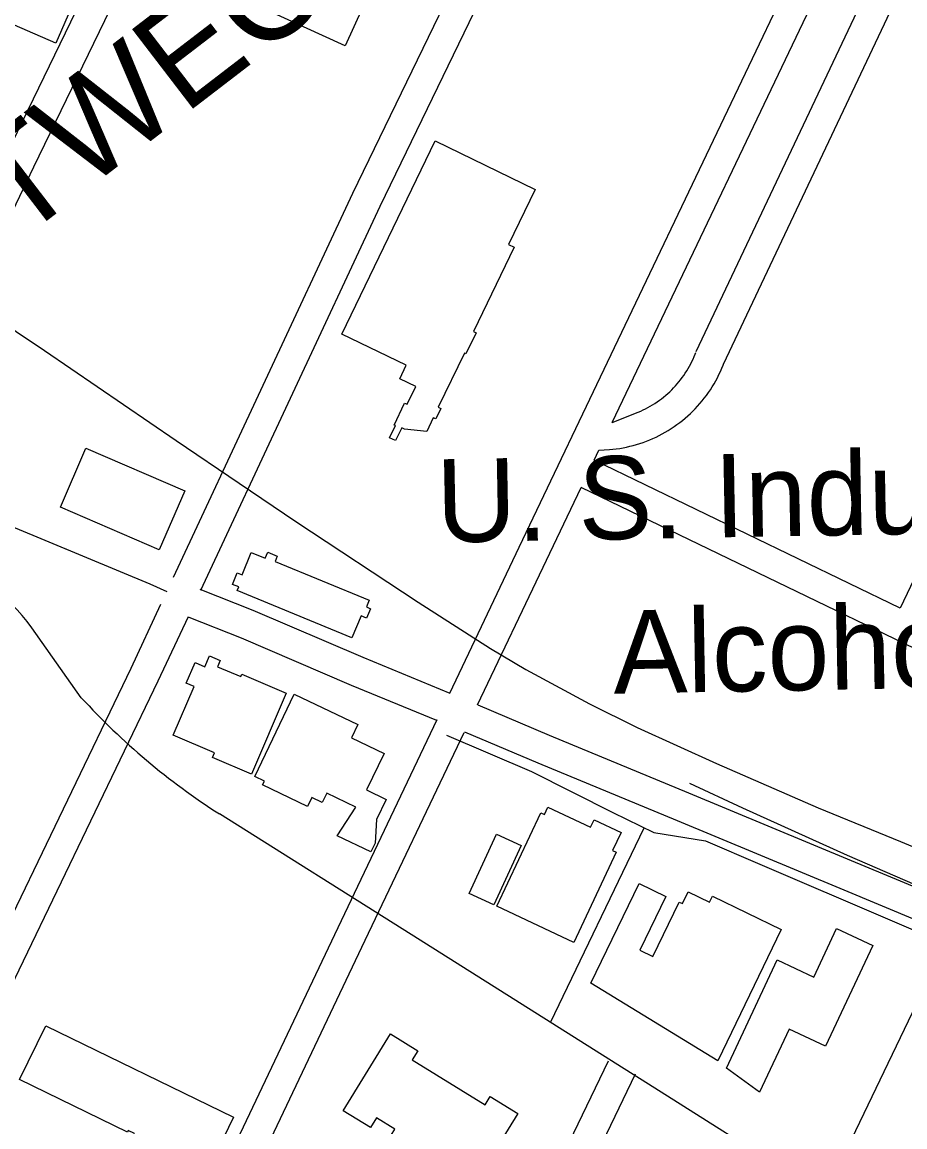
# Model space of a CAD drawing. Extents: x 3651524 to 3689615, y 505651 to 531377.
# Drawn here: x 3657229 to 3658111, y 514096 to 515199 of the extents above; entities that cross this region are included whole.
import ezdxf

# ---------------------------------------------------------------- set-up
doc = ezdxf.new("R2010")
doc.units = 0
for name, color, linetype in [('V-BLDG-IDEN', 7, 'Continuous'), ('V-BLDG-OTLN', 7, 'Continuous'), ('V-CHAN-NAID', 7, 'Continuous'), ('V-RAIL-TRAK', 7, 'Continuous'), ('V-ROAD-CNTR', 7, 'Continuous'), ('V-TOPO-SHOR', 7, 'Continuous')]:
    doc.layers.add(name, color=color, linetype=linetype)

msp = doc.modelspace()

# ---------------------------------------------------------------- linework, layer by layer
at = {"layer": 'V-BLDG-OTLN'}
for points in [[(3657551.585, 515175.671), (3657354.48, 515265.825), (3657380.175, 515322.001), (3657516.958, 515259.436), (3657508.578, 515241.115), (3657568.899, 515213.526)], [(3657219.76, 515292.521), (3657297.426, 515258.969), (3657262.587, 515178.324), (3657184.921, 515211.876)], [(3657641.574, 515080.801), (3657741.612, 515032.389), (3657715.017, 514977.43), (3657720.653, 514974.705), (3657679.855, 514890.397), (3657682.534, 514889.1), (3657672.398, 514868.159), (3657670.848, 514868.909), (3657644.683, 514814.844), (3657647.179, 514813.633), (3657642.147, 514803.236), (3657639.796, 514804.374), (3657633.214, 514790.772), (3657611.022, 514792.865), (3657608.22, 514794.221), (3657602.088, 514781.55), (3657596.096, 514784.449), (3657601.908, 514796.463), (3657600.563, 514797.114), (3657611.136, 514818.962), (3657613.571, 514817.785), (3657622.208, 514835.627), (3657606.193, 514843.377), (3657612.685, 514856.789), (3657548.257, 514887.968)], [(3657365.81, 514672.352), (3657267.153, 514714.95), (3657292.709, 514774.137), (3657391.366, 514731.54)], [(3657558.378, 514584.45), (3657443.889, 514631.763), (3657445.402, 514635.425), (3657439.219, 514637.979), (3657443.956, 514649.445), (3657448.623, 514647.516), (3657457.85, 514669.841), (3657471.881, 514664.046), (3657474.381, 514670.099), (3657483.827, 514666.198), (3657481.668, 514660.976), (3657575.638, 514622.143), (3657572.855, 514615.412), (3657577.056, 514613.677), (3657573.171, 514604.275), (3657567.53, 514606.603)], [(3657492.893, 514529.34), (3657458.184, 514448.383), (3657419.167, 514465.111), (3657421.127, 514469.684), (3657379.821, 514487.393), (3657400.663, 514536.007), (3657392.969, 514539.306), (3657401.782, 514559.858), (3657411.571, 514555.659), (3657416.269, 514566.62), (3657426.796, 514562.104), (3657424.093, 514555.798), (3657447.366, 514545.821), (3657448.468, 514548.389)], [(3657461.307, 514446.101), (3657500.862, 514528.435), (3657564.385, 514497.92), (3657558.075, 514484.784), (3657590.572, 514469.17), (3657573.035, 514432.66), (3657592.616, 514423.254), (3657583.032, 514403.298), (3657581.594, 514379.523), (3657577.398, 514370.792), (3657543.737, 514386.965), (3657562.5, 514415.527), (3657533.368, 514429.521), (3657528.844, 514420.102), (3657518.272, 514425.183), (3657513.967, 514416.219), (3657469.261, 514437.694), (3657471.051, 514441.42)], [(3657780.156, 514280.381), (3657703.284, 514316.492), (3657747.101, 514409.77), (3657750.767, 514408.048), (3657754.261, 514415.486), (3657796.837, 514395.485), (3657800.37, 514403.005), (3657827.397, 514390.31), (3657818.912, 514372.251), (3657822.515, 514370.557)], [(3657727.547, 514377.262), (3657700.294, 514318.093), (3657675.663, 514329.441), (3657702.915, 514388.608)], [(3657797.195, 514239.671), (3657845.342, 514339.214), (3657872.15, 514326.246), (3657846.253, 514272.703), (3657859.151, 514266.463), (3657885.413, 514320.758), (3657888.642, 514319.195), (3657894.377, 514331.051), (3657915.664, 514320.754), (3657918.58, 514326.787), (3657987.45, 514293.476), (3657923.94, 514162.165)], [(3657932.66, 514154.915), (3657983.328, 514262.988), (3658020.013, 514245.787), (3658042.709, 514294.195), (3658078.852, 514277.25), (3658031.705, 514176.691), (3657995.255, 514193.78), (3657965.844, 514131.047)], [(3658226.052, 514215.017), (3658139.41, 514034.877), (3658054.012, 514075.95), (3658138.961, 514252.572), (3658202.871, 514221.835), (3658204.565, 514225.354)], [(3657252.691, 514197.286), (3657440.257, 514105.8), (3657414.489, 514052.971), (3657340.868, 514088.879), (3657341.196, 514089.553), (3657334.869, 514092.637), (3657334.081, 514091.019), (3657226.463, 514143.509)], [(3657549.85, 514112.263), (3657597.028, 514189.053), (3657624.44, 514172.21), (3657618.812, 514163.056), (3657691.465, 514118.421), (3657696.46, 514126.554), (3657724.098, 514109.576), (3657677.643, 514033.966), (3657651.55, 514049.994), (3657657.161, 514059.13), (3657639.663, 514069.88), (3657617.825, 514034.335), (3657579.19, 514058.071), (3657601.322, 514094.101), (3657583.15, 514105.267), (3657577.146, 514095.494)]]:
    msp.add_lwpolyline(points, close=True, dxfattribs=at)
at = {"layer": 'V-RAIL-TRAK'}
msp.add_lwpolyline([(3656994.076, 515047.747), (3657105.069, 514970.799), (3657166.102, 514928.428), (3657251.364, 514871.481), (3657382.891, 514781.73), (3657445.666, 514738.898), (3657502.343, 514700.625), (3657624.534, 514620.046), (3657696.96, 514574.038), (3657732.292, 514553.056), (3657795.889, 514518.578), (3657843.355, 514494.899), (3657922.647, 514459.028), (3658024.488, 514414.992), (3658106.425, 514381.161), (3658188.117, 514347.101), (3658276.069, 514310.043), (3658352.66, 514278.241), (3658430.613, 514244.758), (3658553.331, 514191.666), (3658647.596, 514153.723), (3658745.038, 514111.927), (3658817.017, 514083.077)], dxfattribs=at)
at = {"layer": 'V-ROAD-CNTR'}
msp.add_line((3657356.593, 514638.677), (3657373.495, 514630.998), dxfattribs=at)
for points in [[(3657458.709, 515573.845), (3657213.181, 515067.513), (3657071.929, 514772.098)], [(3657485.609, 515560.563), (3657240.21, 515054.497), (3657099.543, 514760.302)], [(3657753.126, 515428.715), (3657559.14, 515028.303), (3657379.904, 514644.716)], [(3657780.052, 515415.486), (3657586.23, 515015.413), (3657407.038, 514631.92)], [(3657656.213, 514529.304), (3657725.7, 514675.015), (3658022.431, 515296.413)], [(3657818.427, 514799.58), (3658044.596, 515273.21)], [(3657902.507, 514870.649), (3658084.012, 515254.086)], [(3657929.623, 514857.813), (3658111.004, 515240.989)], [(3658350.891, 515124.593), (3658225.73, 514864.878), (3658106.122, 514614.199)], [(3657818.427, 514799.58), (3657844.547, 514809.997), (3657847.021, 514811.058), (3657849.464, 514812.182), (3657851.88, 514813.372), (3657854.265, 514814.623), (3657856.612, 514815.933), (3657858.929, 514817.307), (3657861.209, 514818.74), (3657863.448, 514820.23), (3657865.652, 514821.78), (3657867.811, 514823.384), (3657869.929, 514825.045), (3657872.005, 514826.761), (3657874.033, 514828.529), (3657876.016, 514830.351), (3657877.952, 514832.222), (3657879.836, 514834.142), (3657881.669, 514836.11), (3657883.453, 514838.129), (3657885.184, 514840.191), (3657886.86, 514842.297), (3657888.481, 514844.446), (3657890.045, 514846.636), (3657891.553, 514848.867), (3657893, 514851.134), (3657894.39, 514853.44), (3657895.719, 514855.782), (3657896.988, 514858.156), (3657898.192, 514860.561), (3657899.335, 514862.998), (3657900.414, 514865.465), (3657901.444, 514867.995), (3657902.057, 514869.595)], [(3657805.181, 514771.839), (3657815.692, 514772.552), (3657819.148, 514772.877), (3657822.593, 514773.292), (3657826.028, 514773.795), (3657829.449, 514774.389), (3657832.85, 514775.07), (3657836.235, 514775.839), (3657839.597, 514776.697), (3657842.936, 514777.64), (3657846.252, 514778.671), (3657849.537, 514779.787), (3657852.793, 514780.988), (3657856.017, 514782.273), (3657859.207, 514783.642), (3657862.362, 514785.094), (3657865.474, 514786.626), (3657868.547, 514788.237), (3657871.58, 514789.931), (3657874.563, 514791.701), (3657877.501, 514793.546), (3657880.392, 514795.47), (3657883.228, 514797.466), (3657886.017, 514799.536), (3657888.747, 514801.679), (3657891.421, 514803.889), (3657894.039, 514806.171), (3657896.594, 514808.517), (3657899.088, 514810.93), (3657901.52, 514813.408), (3657903.887, 514815.948), (3657906.185, 514818.547), (3657908.416, 514821.205), (3657910.576, 514823.921), (3657912.667, 514826.692), (3657914.683, 514829.516), (3657916.627, 514832.391), (3657918.496, 514835.318), (3657920.286, 514838.29), (3657921.999, 514841.306), (3657923.634, 514844.368), (3657925.19, 514847.473), (3657926.663, 514850.616), (3657928.054, 514853.795), (3657929.348, 514856.973), (3657930.073, 514858.867)], [(3657800.421, 514761.872), (3657805.181, 514771.839)], [(3658106.122, 514614.198), (3657800.421, 514761.872)], [(3657093.017, 514746.653), (3657187.856, 514708.356), (3657356.593, 514638.677)], [(3657683.934, 514517.736), (3657752.775, 514662.095), (3657787.494, 514734.801)], [(3658326.616, 514474.367), (3657787.494, 514734.801)], [(3657406.585, 514633.102), (3657459.327, 514612.257), (3657569.397, 514565.127), (3657656.298, 514529.269)], [(3657367.31, 514617.763), (3657337.533, 514554.037), (3657202.094, 514273.057)], [(3657394.766, 514605.657), (3657364.635, 514541.173), (3657128.782, 514051.876), (3657054.663, 513895.047)], [(3657395.559, 514605.202), (3657447.907, 514584.513), (3657557.771, 514537.471), (3657643.045, 514502.284)], [(3657288.079, 514524.834), (3657238.636, 514594.592)], [(3657684.317, 514517.575), (3657755.669, 514487.457), (3657894.893, 514429.912), (3658057.369, 514362.283), (3658176.74, 514312.546), (3658283.629, 514266.509), (3658406.475, 514216.451), (3658515.929, 514168.451), (3658524.704, 514164.902)], [(3657286.197, 513751.569), (3657541.362, 514288.466), (3657643.609, 514502.874)], [(3657311.856, 513735.67), (3657568.45, 514275.57), (3657670.763, 514490.118)], [(3657670.853, 514490.695), (3657744.107, 514459.775), (3657883.399, 514402.202), (3658045.835, 514334.589), (3658165.036, 514284.922), (3658272.035, 514238.839), (3658394.789, 514188.819), (3658504.279, 514140.801), (3658596.431, 514103.54), (3658695.192, 514063.878)], [(3657652.918, 514487.544), (3657737.761, 514451.131), (3657819.024, 514410.3), (3657860.265, 514390.116), (3657911.744, 514381.897), (3657965.9, 514358.525), (3658225.725, 514247.41), (3658261.729, 514224.127), (3658297.115, 514216.078), (3658400.681, 514174.504), (3658504.263, 514132.519), (3658750.264, 514026.616)], [(3660002.483, 512788.17), (3659920.129, 512835.555), (3659811.357, 512903.727), (3659420.614, 513150.995), (3658813.631, 513533.008), (3658385.648, 513803.509), (3657867.496, 514130.977), (3657617.757, 514288.284), (3657426.018, 514408.766)], [(3657756.973, 514200.594), (3657850.427, 514394.931)], [(3657541.856, 513591.559), (3657659.049, 513838.743), (3657814.813, 514162.158)], [(3657567.442, 513575.498), (3657686.117, 513825.809), (3657841.841, 514149.14)]]:
    msp.add_lwpolyline(points, dxfattribs=at)
for centre, radius, start, end in [((3657100.261, 514496.31), 169.726, 35.384505, 77.242963), ((3657799.721, 514992.886), 693.433, 222.452435, 237.390093)]:
    msp.add_arc(centre, radius, start, end, dxfattribs=at)
at = {"layer": 'V-TOPO-SHOR'}
msp.add_lwpolyline([(3657895.86, 514439.583), (3657948.565, 514414.917), (3658053.275, 514367.641), (3658178.641, 514313.412), (3658301.112, 514264.608), (3658461.362, 514193.857)], dxfattribs=at)

# ---------------------------------------------------------------- texts
at = {"layer": 'V-BLDG-IDEN'}
for s, p in [('U. S. Industrial', (3657643.42, 514679.79)), ('Alcohol Co.', (3657820.158, 514528.806))]:
    msp.add_text(s, height=82.99983, rotation=1.0368, dxfattribs=at).set_placement(p)
at = {"layer": 'V-CHAN-NAID'}
msp.add_text('WESTWEGO TRAFFIC LIGHT (101.4)', height=100, rotation=37.493815, dxfattribs=at).set_placement((3656984.322, 514794.391))

doc.saveas('drawing.dxf')
